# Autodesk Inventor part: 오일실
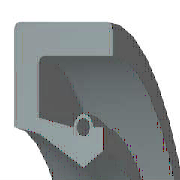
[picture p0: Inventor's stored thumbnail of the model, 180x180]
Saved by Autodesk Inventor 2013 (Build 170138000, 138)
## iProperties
Created: 2009-02
Part Number: 오일실
Material: 고무
Description: 오일-실
Document SubType Name: Modeling
Standard: KS B 2804
Designer: 한국산업디자인학원-SeoGD™
Standards Organization: KS
Language: ko-KR
Size Designation: S - 12 22 7
Categories: <MemberInstance><Categories><Category DisplayName="샤프트 부품" InternalName="7f7aeb1f-a693-4053-b835-cee3144e0d98" Mnemonic="SHFT"><Category DisplayName="실링" Intern
Density: 0.93 g/cm^3
IsCustomPart: 1
Author: 진현석
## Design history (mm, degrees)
revolve "본체" stored, may be unused: angle "d17" = 90 deg
revolve "스프링1" stored, may be unused: angle "d18" = 90 deg
body "Solid1"
sketch "스케치1"
  geometry: L1 (0, 11)-(7, 11); L2 (7, 11)-(7, 9.75); L3 (7, 9.75)-(1.75, 9.75); L4 (0, 11)-(0, 8.1); L5 (0, 8.1)-(1.75, 7.75); L6 (1.75, 7.75)-(4.9, 6); L7 (4.9, 6)-(0, 6); L8 (6.3, 6.875)-(6.3, 8.1); L9 (0, 0)-(9.586, 0) reference; L10 (4.9, 6)-(6.3, 6.875); L11 (0, 18)-(0, -3) reference; L12 (-1.917, 0)-(11.503, 0) reference; L13 (4.2, 8.1)-(1.75, 8.59); L14 (1.75, 8.59)-(1.75, 9.75); L15 (6.3, 8.1)-(5.6, 8.1); C1 r 0.455 at (4.9, 8.1); A1 r 0.7 centre (4.9, 8.1) between (5.6, 8.1) and (4.2, 8.1)
  constraints: 26 end point, 5 horizontal alignment, 4 perpendicular, 2 centre point, 2 collinear, 2 horizontal, 2 parallel, 2 point on circle, 2 point on line, 2 vertical alignment, 1 coincident
  dimensions: "d0" = 22 diameter of L1 L9 (= SD2); "d1" = 13.75 diameter of L8.start L9 (= ABDM); "d2" = 1.25 distance of L1.end L2.end (computed from SD); "d3" = 0.91 diameter of C1 (= SPDI); "d4" = 1.4 diameter of A1 (= SPDA); "d5" = 12 diameter of L6.end L9 (= NND); "d6" = 15.5 diameter of L5.end L9 (= TKDM); "d7" = 16.2 diameter of L4.end L9 (= HLDM); "d8" = 4.9 distance from line of C1.centre L4 (= SPDST); "d9" = 6.3 distance between parallel lines of L8 L4 (= SDI); "d10" = 7 distance between parallel lines of L2 L4 (= SWDT); "d12" = 1.75 distance between parallel lines of L14 L4 (= SD)
fillet "모깎기1" dims "d11" = 0.3 (= RR)
other parameters: "SD2" = 22 [user parameter; used in 1 equation term], "SWDT" = 7 [user parameter; used in 1 equation term], "RR" = 0.3 [user parameter; used in 1 equation term], "SD" = 1.75 [user parameter; used in 2 equation terms], "NND" = 12 [user parameter; used in 1 equation term], "SPDA" = 1.4 [user parameter; used in 1 equation term], "SPDI" = 0.91 [user parameter; used in 1 equation term], "TKDM" = 15.5 [user parameter; used in 1 equation term], "HLDM" = 16.2 [user parameter; used in 1 equation term], "ABDM" = 13.75 [user parameter; used in 1 equation term], "SDI" = 6.3 [user parameter; used in 1 equation term], "SPDST" = 4.9 [user parameter; used in 1 equation term], "d13" = 0, "d14" = 0, "d15" = 0, "LAB" = 0.35 [user parameter]
